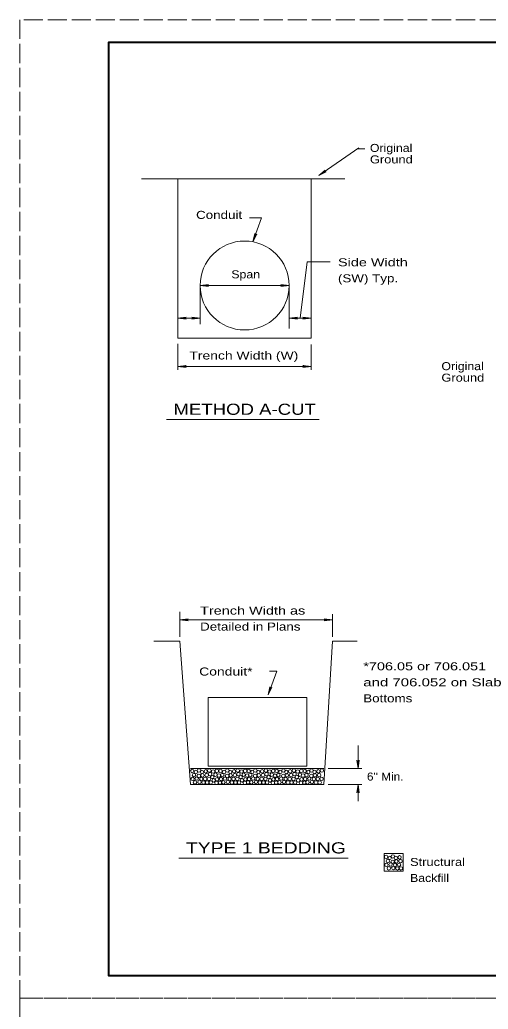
# Model space of a CAD drawing. Extents: x 750.7 to 784.7, y 834.8 to 878.8.
# Drawn here: x 750.65 to 761.19, y 856.53 to 878.78 of the extents above; entities that cross this region are included whole.
import ezdxf

# ---------------------------------------------------------------- set-up
doc = ezdxf.new("R2010")
doc.units = 0
doc.header["$LTSCALE"] = 0.072
doc.linetypes.add('LONG_DASHED', pattern=[7.5, 6, -1.5])
doc.layers.add('1', color=7, linetype='Continuous', lineweight=13)
doc.layers.add('47', color=7, linetype='Continuous', lineweight=13)

msp = doc.modelspace()

# ---------------------------------------------------------------- linework, layer by layer
at = {"layer": '1', "lineweight": 40}
msp.add_line((752.65083, 878.28433), (784.15083, 878.28433), dxfattribs=at)
at = {"layer": '1'}
for p, q in [((757.37717, 875.2795), (758.27367, 875.90675)), ((758.24358, 875.88567), (758.41, 875.88567)), ((753.38525, 875.20733), (757.96117, 875.20733)), ((754.20825, 875.20733), (754.20825, 871.62408)), ((757.20825, 875.20733), (757.20825, 871.62408)), ((754.70825, 872.80942), (754.70825, 871.93608)), ((754.70825, 872.80942), (756.70825, 872.80942)), ((756.70825, 872.80942), (756.70825, 871.8425)), ((754.20825, 872.07242), (754.70825, 872.07242)), ((756.70825, 872.07242), (757.20825, 872.07242)), ((754.20825, 871.62408), (757.20825, 871.62408)), ((754.20825, 871.49767), (754.20825, 870.91208)), ((757.20825, 871.482), (757.20825, 870.91208)), ((754.20825, 870.99008), (757.20825, 870.99008)), ((753.94758, 869.79475), (757.38325, 869.79475)), ((754.24825, 865.469), (754.24825, 864.9075)), ((757.68658, 865.4205), (757.68658, 864.9075)), ((754.24825, 865.28958), (757.68658, 865.28958)), ((753.66592, 864.81083), (754.24825, 864.81083)), ((754.24825, 864.81083), (754.48892, 861.58825)), ((757.68658, 864.81083), (757.48892, 861.58825)), ((757.68658, 864.81083), (758.24183, 864.81083)), ((758.25875, 861.94608), (758.25875, 862.46792)), ((754.48892, 861.94608), (757.48892, 861.94608)), ((757.58517, 861.94608), (758.3415, 861.94608)), ((754.48892, 861.58825), (757.48892, 861.58825)), ((757.58517, 861.58825), (758.3415, 861.58825)), ((758.25875, 861.58825), (758.25875, 861.21483)), ((758.84925, 860.03258), (758.84925, 859.63858)), ((758.84925, 860.03258), (759.27733, 860.03258)), ((759.27733, 860.03258), (759.27733, 859.63858)), ((754.22825, 859.93142), (758.03425, 859.93142)), ((758.84925, 859.63858), (759.27733, 859.63858))]:
    msp.add_line(p, q, dxfattribs=at)
at = {"layer": '1', "lineweight": 25}
msp.add_line((784.15083, 857.28433), (752.65083, 857.28433), dxfattribs=at)
at = {"layer": '1', "linetype": 'LONG_DASHED'}
for points in [[(750.65083, 856.78433), (784.65083, 856.78433), (784.65083, 878.78433), (750.65083, 878.78433)], [(750.65083, 834.78433), (784.65083, 834.78433), (784.65083, 856.78433), (750.65083, 856.78433)]]:
    msp.add_lwpolyline(points, close=True, dxfattribs=at)
at = {"layer": '1', "lineweight": 40}
for points in [[(784.15083, 857.28433), (752.65083, 857.28433), (752.65083, 878.28433), (784.15083, 878.28433)], [(784.15083, 857.28433), (752.65083, 857.28433), (752.65083, 878.28433)]]:
    msp.add_lwpolyline(points, dxfattribs=at)
at = {"layer": '1'}
for points in [[(755.81583, 874.3295), (756.08867, 874.3295), (755.89433, 873.79192)], [(756.954, 872.07242), (757.11775, 873.33908), (757.63225, 873.33908)], [(756.26575, 864.13942), (756.4295, 864.13942), (756.23517, 863.60183)]]:
    msp.add_lwpolyline(points, dxfattribs=at)
msp.add_lwpolyline([(754.88817, 863.54517), (757.10583, 863.54517), (757.10583, 861.99733), (754.88817, 861.99733)], close=True, dxfattribs=at)
for centre, radius in [((755.70825, 872.80942), 1), ((754.52958, 861.89242), 0.03892), ((754.53738, 861.71306), 0.03892), ((754.56855, 861.79881), 0.03892), ((754.61136, 861.86899), 0.03892), ((754.63088, 861.72081), 0.03892), ((754.67772, 861.78323), 0.03892), ((754.68163, 861.90223), 0.03892), ((754.7323, 861.71115), 0.03892), ((754.74788, 861.86898), 0.03892), ((754.75963, 861.79306), 0.03892), ((754.82197, 861.71506), 0.03892), ((754.83372, 861.88273), 0.03892), ((754.85313, 861.7969), 0.03892), ((754.90772, 861.71506), 0.03892), ((754.91555, 861.90223), 0.03892), ((754.93113, 861.82031), 0.03892), ((754.9818, 861.7579), 0.03892), ((755.0013, 861.87881), 0.03892), ((755.05197, 861.80865), 0.03892), ((755.08313, 861.8944), 0.03892), ((755.12764, 861.79098), 0.03892), ((755.16667, 861.89242), 0.03892), ((755.17447, 861.71306), 0.03892), ((755.20563, 861.79881), 0.03892), ((755.24844, 861.86899), 0.03892), ((755.26797, 861.72081), 0.03892), ((755.3148, 861.78323), 0.03892), ((755.31872, 861.90223), 0.03892), ((755.36938, 861.71115), 0.03892), ((755.38497, 861.86898), 0.03892), ((755.39672, 861.79306), 0.03892), ((755.45905, 861.71506), 0.03892), ((755.4708, 861.88273), 0.03892), ((755.49022, 861.7969), 0.03892), ((755.5448, 861.71506), 0.03892), ((755.55263, 861.90223), 0.03892), ((755.56822, 861.82031), 0.03892), ((755.61888, 861.7579), 0.03892), ((755.63838, 861.87881), 0.03892), ((755.68905, 861.80865), 0.03892), ((755.72022, 861.8944), 0.03892), ((755.76689, 861.79098), 0.03892), ((755.79808, 861.89242), 0.03892), ((755.80588, 861.71306), 0.03892), ((755.83705, 861.79881), 0.03892), ((755.87986, 861.86899), 0.03892), ((755.89938, 861.72081), 0.03892), ((755.94622, 861.78323), 0.03892), ((755.95013, 861.90223), 0.03892), ((756.0008, 861.71115), 0.03892), ((756.01638, 861.86898), 0.03892), ((756.02813, 861.79306), 0.03892), ((756.09047, 861.71506), 0.03892), ((756.10222, 861.88273), 0.03892), ((756.12163, 861.7969), 0.03892), ((756.17622, 861.71506), 0.03892), ((756.18405, 861.90223), 0.03892), ((756.19963, 861.82031), 0.03892), ((756.2503, 861.7579), 0.03892), ((756.2698, 861.87881), 0.03892), ((756.32047, 861.80865), 0.03892), ((756.35163, 861.8944), 0.03892), ((756.39056, 861.78714), 0.03892), ((756.4295, 861.89242), 0.03892), ((756.4373, 861.71306), 0.03892), ((756.46847, 861.79881), 0.03892), ((756.51128, 861.86899), 0.03892), ((756.5308, 861.72081), 0.03892), ((756.57763, 861.78323), 0.03892), ((756.58155, 861.90223), 0.03892), ((756.63222, 861.71115), 0.03892), ((756.6478, 861.86898), 0.03892), ((756.65955, 861.79306), 0.03892), ((756.72188, 861.71506), 0.03892), ((756.73363, 861.88273), 0.03892), ((756.75305, 861.7969), 0.03892), ((756.80763, 861.71506), 0.03892), ((756.81547, 861.90223), 0.03892), ((756.83105, 861.82031), 0.03892), ((756.88172, 861.7579), 0.03892), ((756.90122, 861.87881), 0.03892), ((756.95188, 861.80865), 0.03892), ((756.98305, 861.8944), 0.03892), ((757.02198, 861.79098), 0.03892), ((757.061, 861.89242), 0.03892), ((757.0688, 861.71306), 0.03892), ((757.09997, 861.79881), 0.03892), ((757.14278, 861.86899), 0.03892), ((757.1623, 861.72081), 0.03892), ((757.20913, 861.78323), 0.03892), ((757.21305, 861.90223), 0.03892), ((757.26372, 861.71115), 0.03892), ((757.2793, 861.86898), 0.03892), ((757.29105, 861.79306), 0.03892), ((757.35338, 861.71506), 0.03892), ((757.36513, 861.88273), 0.03892), ((757.38455, 861.7969), 0.03892), ((757.43913, 861.71506), 0.03892), ((757.44697, 861.90223), 0.03892), ((754.59197, 861.63506), 0.03892), ((754.6933, 861.6429), 0.03892), ((754.78297, 861.63315), 0.03892), ((754.86488, 861.63315), 0.03892), ((754.94672, 861.63315), 0.03892), ((755.01297, 861.67998), 0.03892), ((755.0753, 861.6254), 0.03892), ((755.08705, 861.70331), 0.03892), ((755.15498, 861.63114), 0.03892), ((755.22905, 861.63506), 0.03892), ((755.33038, 861.6429), 0.03892), ((755.42005, 861.63315), 0.03892), ((755.50197, 861.63315), 0.03892), ((755.5838, 861.63315), 0.03892), ((755.65005, 861.67998), 0.03892), ((755.71238, 861.6254), 0.03892), ((755.72413, 861.70331), 0.03892), ((755.78639, 861.63506), 0.03892), ((755.86047, 861.63506), 0.03892), ((755.9618, 861.6429), 0.03892), ((756.05147, 861.63315), 0.03892), ((756.13338, 861.63315), 0.03892), ((756.21522, 861.63315), 0.03892), ((756.28147, 861.67998), 0.03892), ((756.3438, 861.6254), 0.03892), ((756.35555, 861.70331), 0.03892), ((756.35555, 861.70331), 0.03892), ((756.41781, 861.63114), 0.03892), ((756.49188, 861.63506), 0.03892), ((756.59322, 861.6429), 0.03892), ((756.68288, 861.63315), 0.03892), ((756.7648, 861.63315), 0.03892), ((756.84663, 861.63315), 0.03892), ((756.91288, 861.67998), 0.03892), ((756.97522, 861.6254), 0.03892), ((756.98697, 861.70331), 0.03892), ((756.98705, 861.70331), 0.03892), ((756.98705, 861.70331), 0.03892), ((757.04931, 861.63114), 0.03892), ((757.12338, 861.63506), 0.03892), ((757.22472, 861.6429), 0.03892), ((757.31438, 861.63315), 0.03892), ((757.3963, 861.63315), 0.03892), ((758.88992, 859.96), 0.03892), ((758.97169, 859.93658), 0.03892), ((759.04197, 859.96981), 0.03892), ((759.10822, 859.93656), 0.03892), ((759.19405, 859.95031), 0.03892), ((758.89772, 859.78065), 0.03892), ((758.92888, 859.8664), 0.03892), ((758.9523, 859.70265), 0.03892), ((758.99122, 859.7884), 0.03892), ((759.03805, 859.85081), 0.03892), ((759.05363, 859.71048), 0.03892), ((759.09263, 859.77873), 0.03892), ((759.11997, 859.86065), 0.03892), ((759.1823, 859.78265), 0.03892), ((759.21347, 859.86448), 0.03892), ((759.1433, 859.70073), 0.03892), ((759.22522, 859.70073), 0.03892)]:
    msp.add_circle(centre, radius, dxfattribs=at)
at = {"layer": '47'}
for points in [[(757.54425, 875.36783), (757.37717, 875.2795), (757.51733, 875.40617)], [(755.98008, 873.96025), (755.89433, 873.79192), (755.93608, 873.97625)], [(754.89575, 872.786), (754.70825, 872.80942), (754.89575, 872.83283)], [(756.52075, 872.83283), (756.70825, 872.80942), (756.52075, 872.786)], [(754.39575, 872.049), (754.20825, 872.07242), (754.39575, 872.09583)], [(754.52075, 872.09583), (754.70825, 872.07242), (754.52075, 872.049)], [(756.89575, 872.049), (756.70825, 872.07242), (756.89575, 872.09583)], [(757.02075, 872.09583), (757.20825, 872.07242), (757.02075, 872.049)], [(754.39575, 870.96667), (754.20825, 870.99008), (754.39575, 871.0135)], [(757.02075, 871.0135), (757.20825, 870.99008), (757.02075, 870.96667)], [(754.43575, 865.26617), (754.24825, 865.28958), (754.43575, 865.313)], [(757.49908, 865.313), (757.68658, 865.28958), (757.49908, 865.26617)], [(756.32092, 863.77017), (756.23517, 863.60183), (756.27692, 863.78617)], [(758.28217, 862.13358), (758.25875, 861.94608), (758.23533, 862.13358)], [(758.23533, 861.40075), (758.25875, 861.58825), (758.28217, 861.40075)]]:
    msp.add_lwpolyline(points, dxfattribs=at)
for centre, start, end in [((757.5308, 875.387), 124.97915, 304.97915), ((755.95807, 873.96826), 160.12536, 340.12536), ((754.89576, 872.80942), 90, 270), ((756.52074, 872.80941), 270, 90), ((754.39576, 872.07242), 90, 270), ((754.52074, 872.07241), 270, 90), ((756.89576, 872.07242), 90, 270), ((757.02074, 872.07241), 270, 90), ((754.39576, 870.99009), 90, 270), ((757.02074, 870.99008), 270, 90), ((754.43574, 865.28963), 90, 270), ((757.49911, 865.28961), 270, 90), ((756.29891, 863.77817), 160.12536, 340.12536), ((758.25874, 862.13359), 180, 0), ((758.25876, 861.40074), 0, 180)]:
    msp.add_arc(centre, 0.02342, start, end, dxfattribs=at)

# ---------------------------------------------------------------- texts
at = {"layer": '1'}
for s, height, width, p in [('Original', 0.18, 1.15, (758.52658, 875.8125)), ('Ground', 0.18, 1.2, (758.52658, 875.5545)), ('Conduit', 0.18, 1.25, (754.61583, 874.30683)), ('Side Width ', 0.18, 1.35, (757.80758, 873.241)), ('Span', 0.18, 1.15, (755.409, 872.97075)), ('(SW) Typ.', 0.18, 1.25, (757.80758, 872.881)), ('Trench Width (W)', 0.18, 1.3, (754.46492, 871.14483)), ('Original', 0.18, 1.15, (760.13467, 870.90533)), ('Ground', 0.18, 1.2, (760.13467, 870.64733)), ('METHOD A-CUT', 0.25, 1.25, (754.107, 869.90108)), ('Trench Width as ', 0.18, 1.35, (754.70658, 865.40833)), ('Detailed in Plans', 0.18, 1.25, (754.70658, 865.04833)), ('Conduit*', 0.18, 1.3, (754.68567, 864.038)), ('*706.05 or 706.051', 0.18, 1.35, (758.37692, 864.15567)), ('and 706.052 on Slab ', 0.18, 1.4, (758.37692, 863.79567)), ('Bottoms', 0.18, 1.25, (758.37692, 863.43567)), ("6'' Min.", 0.18, 1.1, (758.45967, 861.67583)), ('TYPE 1 BEDDING', 0.25, 1.3, (754.38767, 860.03775)), ('Structural', 0.18, 1.2, (759.42917, 859.75567)), ('Backfill', 0.18, 1.15, (759.42917, 859.39567))]:
    msp.add_text(s, height=height, dxfattribs=dict(at, width=width)).set_placement(p)

doc.saveas('drawing.dxf')
